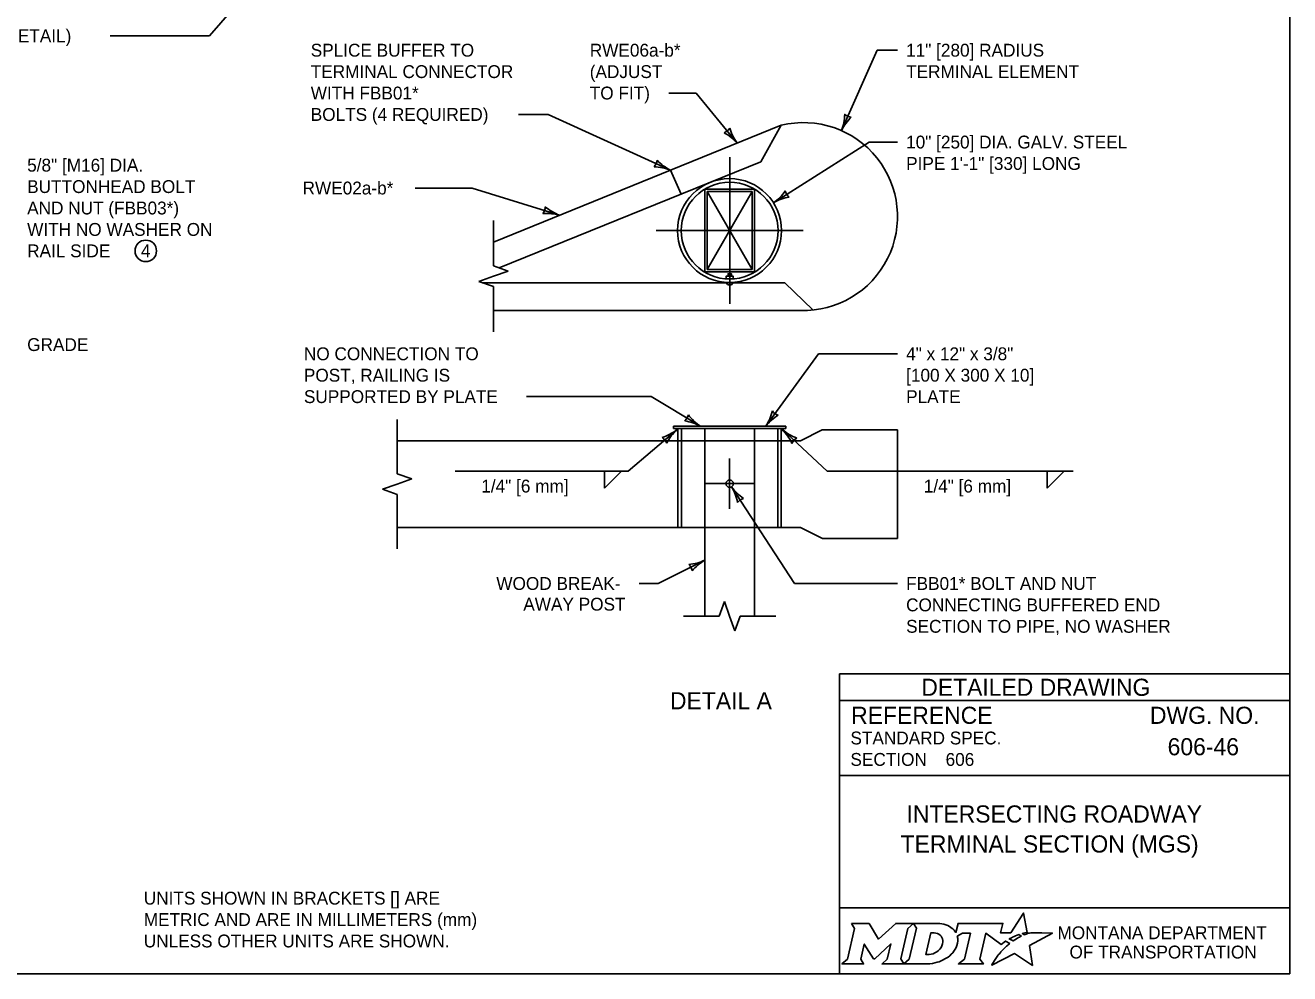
# Model space of a CAD drawing. Extents: x 49991.4 to 50021, y 49987.6 to 50011.4.
# Drawn here: x 50010.85 to 50016.75, y 49987.8 to 49992.23 of the extents above; entities that cross this region are included whole.
import ezdxf

# ---------------------------------------------------------------- set-up
doc = ezdxf.new("R2010")
doc.units = 0
for name, color, linetype in [('Default', 7, 'Continuous'), ('Level 1', 7, 'Continuous'), ('Level 2', 7, 'Continuous'), ('Level 3', 7, 'Continuous'), ('Level 4', 7, 'Continuous'), ('Level 5', 7, 'Continuous'), ('Level 6', 7, 'Continuous')]:
    doc.layers.add(name, color=color, linetype=linetype)

msp = doc.modelspace()

# ---------------------------------------------------------------- linework, layer by layer
at = {"layer": 'Default'}
for points in [[(50015.5126, 49987.9811), (50015.5023, 49987.9867), (50015.5139, 49987.9895), (50015.5255, 49987.9915), (50015.5081, 49988.0816), (50015.4486, 49987.9903), (50015.4013, 49987.9896), (50015.4116, 49988.0337), (50015.2024, 49988.0338), (50015.1923, 49987.9913), (50015.1865, 49987.9996)], [(50014.7056, 49988.0338), (50014.7197, 49988.0104), (50014.6862, 49987.8671), (50014.6605, 49987.8446), (50014.7621, 49987.8446), (50014.7486, 49987.8674), (50014.7648, 49987.9375), (50014.8085, 49987.8685), (50014.8138, 49987.8685), (50014.8889, 49987.938), (50014.8725, 49987.8669), (50014.8478, 49987.8449), (50014.9494, 49987.8449), (50014.9356, 49987.8682), (50014.9688, 49988.0106)], [(50014.9688, 49988.0106), (50014.9941, 49988.0338), (50014.9117, 49988.0338), (50014.8321, 49987.9608), (50014.7876, 49988.0335), (50014.7056, 49988.0338)], [(50015.1077, 49988.0338), (50014.9941, 49988.0338), (50015.0088, 49988.0109), (50014.9749, 49987.8671), (50014.9494, 49987.8449), (50015.06, 49987.8449)], [(50015.1317, 49987.9471), (50015.1305, 49987.939), (50015.1273, 49987.9297), (50015.1231, 49987.9215), (50015.1175, 49987.914), (50015.111, 49987.9071), (50015.1031, 49987.9008), (50015.0948, 49987.8961), (50015.0857, 49987.8922), (50015.0766, 49987.8899), (50015.0674, 49987.889), (50015.0515, 49987.889), (50015.0751, 49987.989), (50015.0911, 49987.989), (50015.0987, 49987.9884), (50015.1063, 49987.9865), (50015.1129, 49987.9835), (50015.119, 49987.9793), (50015.1238, 49987.9743), (50015.1275, 49987.9683), (50015.1302, 49987.9621), (50015.1318, 49987.9547), (50015.1318, 49987.9517), (50015.1317, 49987.9471)], [(50015.1991, 49987.9747), (50015.2237, 49987.9878), (50015.2606, 49987.9878), (50015.232, 49987.8673), (50015.2045, 49987.8446), (50015.3207, 49987.8446), (50015.3037, 49987.8675), (50015.3319, 49987.9877), (50015.4032, 49987.936), (50015.4243, 49987.9511), (50015.444, 49987.9402)], [(50015.3882, 49987.8843), (50015.3729, 49987.8599), (50015.3682, 49987.8524), (50015.3624, 49987.8438), (50015.3601, 49987.8395), (50015.4654, 49987.8926), (50015.5493, 49987.8375), (50015.5362, 49987.9302), (50015.6431, 49987.9886), (50015.5938, 49987.9894), (50015.5637, 49987.9898), (50015.5429, 49987.9901), (50015.5361, 49987.9886), (50015.5312, 49987.9874), (50015.5228, 49987.9851), (50015.5126, 49987.9811)], [(50015.4622, 49987.9535), (50015.4598, 49987.9518), (50015.4415, 49987.9614), (50015.4518, 49987.9671), (50015.4559, 49987.9693), (50015.4645, 49987.9733), (50015.4702, 49987.9759), (50015.4781, 49987.9789), (50015.4854, 49987.9816), (50015.4972, 49987.9742), (50015.4932, 49987.9721), (50015.4886, 49987.9696), (50015.4844, 49987.9674), (50015.4794, 49987.9645), (50015.4775, 49987.9634), (50015.4748, 49987.9618), (50015.4723, 49987.9604), (50015.47, 49987.9588), (50015.4674, 49987.957), (50015.4647, 49987.9552), (50015.4622, 49987.9535)], [(50015.1057, 49987.8522), (50015.1141, 49987.8548), (50015.1271, 49987.8602), (50015.1475, 49987.8712)], [(50015.4021, 49987.9004), (50015.4021, 49987.9004)]]:
    msp.add_lwpolyline(points, dxfattribs=at)
for centre, radius, start, end in [((50015.0868, 49987.9727), 0.1183, 300.91025, 339.13831), ((50015.1308, 49987.9554), 0.0709, 339.53292, 15.85821)]:
    msp.add_arc(centre, radius, start, end, dxfattribs=at)
for centre, major_axis, ratio, start_param, end_param in [((50015.1056, 49987.9864), (0.0834, -0.0037), 0.568097, 0.61298, 1.570796), ((50015.1612, 49987.9937), (0.0361, -0.0295), 0.469099, 1.225588, 1.570796), ((50015.4119, 49987.9106), (-0.0098, -0.0102), 0.016458, 3.141593, 6.279097), ((50015.4329, 49987.9305), (-0.0112, -0.0097), 0.021651, 3.157348, 6.283185), ((50015.3952, 49987.8923), (-0.00694, -0.00806), 0.008222, 0, 3.137361), ((50015.0603, 49987.9932), (0, 0.1484), 0.987302, 3.139398, 3.456847)]:
    msp.add_ellipse(centre, major_axis=major_axis, ratio=ratio, start_param=start_param, end_param=end_param, dxfattribs=at)
at = {"layer": 'Level 1'}
for p, q in [((50013.0344, 49991.2151), (50014.3767, 49991.76)), ((50014.2819, 49991.5899), (50014.3767, 49991.76)), ((50013.061, 49991.0947), (50014.2819, 49991.5899)), ((50013.8604, 49991.5504), (50013.9098, 49991.4389)), ((50014.0326, 49991.4504), (50014.2413, 49991.0872)), ((50014.0326, 49991.0872), (50014.2413, 49991.4504)), ((50014.0213, 49991.0757), (50014.2526, 49991.0757)), ((50012.9825, 49991.0253), (50014.3945, 49991.0253)), ((50014.5252, 49990.8978), (50014.3945, 49991.0253)), ((50013.0344, 49990.8959), (50014.4674, 49990.8959)), ((50013.8742, 49990.3549), (50014.3995, 49990.3549)), ((50013.8742, 49990.3549), (50013.8742, 49990.3451)), ((50013.8742, 49990.3451), (50014.3995, 49990.3451)), ((50013.8945, 49990.3451), (50013.8945, 49990.287)), ((50013.9115, 49990.3451), (50013.9115, 49990.287)), ((50014.0212, 49990.3451), (50014.0212, 49990.287)), ((50014.2525, 49990.3451), (50014.2525, 49990.287)), ((50014.3609, 49990.3451), (50014.3609, 49990.287)), ((50014.3779, 49990.3451), (50014.3779, 49990.287)), ((50014.3995, 49990.3549), (50014.3995, 49990.3451)), ((50014.5682, 49990.3383), (50014.4672, 49990.287)), ((50014.5682, 49990.3383), (50014.9202, 49990.3383)), ((50014.9202, 49990.3383), (50014.9202, 49989.8305)), ((50012.5854, 49990.287), (50014.4672, 49990.287)), ((50012.5854, 49989.8827), (50014.4672, 49989.8827)), ((50014.0212, 49989.8827), (50014.0212, 49989.4678)), ((50014.2525, 49989.8827), (50014.2525, 49989.4678)), ((50014.5697, 49989.8305), (50014.4672, 49989.8827)), ((50014.5697, 49989.8305), (50014.9202, 49989.8305))]:
    msp.add_line(p, q, dxfattribs=at)
for points in [[(49999.3835, 49998.9992), (50016.7501, 49998.9992), (50016.7501, 49987.7988), (49999.3835, 49987.7988)], [(50014.0326, 49991.4504), (50014.2413, 49991.4504), (50014.2413, 49991.0872), (50014.0326, 49991.0872)], [(50014.1211, 49991.043), (50014.1211, 49991.0559), (50014.1528, 49991.0559), (50014.1528, 49991.043)], [(50014.1291, 49991.0563), (50014.1291, 49991.0668), (50014.1447, 49991.0668), (50014.1447, 49991.0563)]]:
    msp.add_lwpolyline(points, close=True, dxfattribs=at)
msp.add_lwpolyline([(50014.0213, 49991.2468), (50014.0213, 49991.4619), (50014.2526, 49991.4619), (50014.2526, 49991.0757), (50014.0213, 49991.0757), (50014.0213, 49991.2468)], dxfattribs=at)
for centre, radius in [((50014.1364, 49991.2685), 0.2426), ((50014.1369, 49991.2682), 0.2257), ((50014.1369, 49990.0869), 0.017)]:
    msp.add_circle(centre, radius, dxfattribs=at)
for centre, radius, start, end in [((50014.4814, 49991.3341), 0.4385, 268.1763, 103.80595), ((50014.1369, 49991.0323), 0.018, 202.88216, 337.11784), ((50013.8758, 49990.3264), 0.0188, 0, 85.1307), ((50014.3967, 49990.3264), 0.0188, 94.48831, 180)]:
    msp.add_arc(centre, radius, start, end, dxfattribs=at)
at = {"layer": 'Level 2'}
msp.add_circle((50011.4126, 49991.1739), 0.05, dxfattribs=at)
at = {"layer": 'Level 3'}
for p, q in [((50011.7103, 49992.1778), (50012.0437, 49992.5637)), ((50011.2468, 49992.1778), (50011.7103, 49992.1778)), ((50014.6587, 49991.7352), (50014.8247, 49992.1107)), ((50014.8247, 49992.1107), (50014.9202, 49992.1107)), ((50013.9806, 49991.9107), (50013.8534, 49991.9107)), ((50014.1723, 49991.677), (50013.9806, 49991.9107)), ((50013.2899, 49991.8107), (50013.1509, 49991.8107)), ((50013.8604, 49991.5504), (50013.2899, 49991.8107)), ((50014.3412, 49991.3986), (50014.7882, 49991.6818)), ((50014.7882, 49991.6818), (50014.9202, 49991.6818)), ((50012.9361, 49991.4672), (50012.6691, 49991.4672)), ((50013.3433, 49991.3405), (50012.9361, 49991.4672)), ((50014.5511, 49990.6932), (50014.3052, 49990.3549)), ((50014.5511, 49990.6932), (50014.9202, 49990.6932)), ((50013.1888, 49990.4932), (50013.7711, 49990.4932)), ((50013.7711, 49990.4932), (50014.0007, 49990.3549)), ((50013.8901, 49990.3385), (50013.6634, 49990.1456)), ((50014.3829, 49990.3391), (50014.5922, 49990.1456)), ((50013.6634, 49990.1456), (50012.8554, 49990.1456)), ((50013.5529, 49990.0656), (50013.5529, 49990.1456)), ((50013.5529, 49990.0656), (50013.6329, 49990.1456)), ((50015.7393, 49990.1456), (50014.5922, 49990.1456)), ((50015.6177, 49990.0656), (50015.6177, 49990.1456)), ((50015.6177, 49990.0656), (50015.6977, 49990.1456)), ((50014.1461, 49990.0726), (50014.4392, 49989.6208)), ((50013.8025, 49989.6208), (50014.0212, 49989.73)), ((50013.7145, 49989.6208), (50013.8025, 49989.6208)), ((50014.4392, 49989.6208), (50014.9202, 49989.6208))]:
    msp.add_line(p, q, dxfattribs=at)
for centre, radius, start, end in [((50014.4406, 49991.817), 0.233, 339.43304, 358.68289), ((50014.859, 49991.6386), 0.2223, 134.06174, 154.24525), ((50014.7096, 49991.8528), 0.0548, 228.74455, 264.46691), ((50014.091, 49991.7761), 0.0548, 291.4961, 327.21846), ((50013.9997, 49991.5205), 0.233, 42.18459, 61.43444), ((50014.3499, 49991.8108), 0.2223, 196.81329, 216.9968), ((50013.7438, 49991.6036), 0.0548, 317.60842, 353.33078), ((50013.961, 49991.7487), 0.2223, 222.92561, 243.10912), ((50013.7742, 49991.3339), 0.233, 68.29691, 87.54676), ((50014.2072, 49991.5891), 0.233, 305.13102, 324.38087), ((50014.4522, 49991.2059), 0.2223, 99.75972, 119.94323), ((50014.4496, 49991.4671), 0.0548, 194.44253, 230.16489), ((50013.2214, 49991.3801), 0.0548, 324.10531, 359.82767), ((50013.2822, 49991.1156), 0.233, 74.7938, 94.04365), ((50013.4208, 49991.5488), 0.2223, 229.4225, 249.60601), ((50013.8908, 49990.4209), 0.0548, 311.12742, 346.84978), ((50014.123, 49990.5405), 0.2223, 216.44461, 236.62812), ((50014.1102, 49990.4824), 0.233, 326.81521, 346.06506), ((50014.4795, 49990.2169), 0.2223, 121.44391, 141.62742), ((50014.3806, 49990.4586), 0.0548, 216.12672, 251.84908), ((50013.753, 49990.5136), 0.2223, 287.86756, 308.05106), ((50014.0497, 49990.1688), 0.233, 133.23886, 152.48871), ((50013.8907, 49990.1495), 0.233, 61.81591, 81.06576), ((50014.2254, 49990.1822), 0.2223, 24.70017, 44.88367), ((50014.5325, 49990.5178), 0.233, 230.07147, 249.32132), ((50013.7924, 49990.2554), 0.0548, 22.55036, 58.27272), ((50014.4771, 49990.2521), 0.0548, 119.38297, 155.10534), ((50013.9547, 49989.9594), 0.2223, 10.42663, 30.61014), ((50014.3351, 49990.2089), 0.233, 215.79793, 235.04778), ((50014.2158, 49989.9651), 0.0548, 105.10944, 140.8318), ((50013.9255, 49989.9307), 0.2223, 275.3243, 295.50781), ((50013.9079, 49989.6701), 0.0548, 10.00711, 45.72947), ((50014.1402, 49989.5297), 0.233, 120.6956, 139.94545)]:
    msp.add_arc(centre, radius, start, end, dxfattribs=at)
at = {"layer": 'Level 4'}
for p, q in [((50013.8945, 49990.287), (50013.8945, 49989.8827)), ((50013.9115, 49990.287), (50013.9115, 49989.8827)), ((50014.0212, 49990.287), (50014.0212, 49989.8827)), ((50014.2525, 49990.287), (50014.2525, 49989.8827)), ((50014.3609, 49990.287), (50014.3609, 49989.8827)), ((50014.3779, 49990.287), (50014.3779, 49989.8827))]:
    msp.add_line(p, q, dxfattribs=at)
at = {"layer": 'Level 5'}
for p, q in [((50014.1369, 49991.6117), (50014.1369, 49990.9265)), ((50014.4791, 49991.2688), (50013.7938, 49991.2688)), ((50014.1368, 49989.9699), (50014.1368, 49990.2039)), ((50014.0199, 49990.0869), (50014.2538, 49990.0869)), ((50016.7501, 49989.1988), (50014.6501, 49989.1988)), ((50014.6501, 49989.1988), (50014.6501, 49987.7988)), ((50016.7501, 49989.0738), (50014.6501, 49989.0738)), ((50016.3862, 49988.8587), (50016.3862, 49988.8587)), ((50015.1444, 49988.7993), (50015.1444, 49988.7993)), ((50016.7501, 49988.7238), (50014.6501, 49988.7238)), ((50015.7001, 49988.4747), (50015.7001, 49988.4747)), ((50016.7501, 49988.1057), (50014.6501, 49988.1057))]:
    msp.add_line(p, q, dxfattribs=at)
at = {"layer": 'Level 6'}
for p, q in [((50013.0344, 49991.3151), (50013.0344, 49991.1041)), ((50013.0344, 49991.0555), (50012.9658, 49991.0312)), ((50013.103, 49991.0798), (50013.0344, 49991.1041)), ((50013.103, 49991.0798), (50013.0344, 49991.0555)), ((50013.0344, 49991.0069), (50012.9658, 49991.0312)), ((50013.0344, 49991.0069), (50013.0344, 49990.7959)), ((50012.5854, 49990.387), (50012.5854, 49990.1335)), ((50012.654, 49990.1092), (50012.5854, 49990.1335)), ((50012.654, 49990.1092), (50012.5854, 49990.0849)), ((50012.5854, 49990.0849), (50012.5168, 49990.0606)), ((50012.5854, 49990.0363), (50012.5168, 49990.0606)), ((50012.5854, 49990.0363), (50012.5854, 49989.7827)), ((50014.1125, 49989.5363), (50014.0882, 49989.4678)), ((50014.1125, 49989.5363), (50014.1368, 49989.4678)), ((50013.9212, 49989.4678), (50014.0882, 49989.4678)), ((50014.1368, 49989.4678), (50014.1611, 49989.3993)), ((50014.1854, 49989.4678), (50014.1611, 49989.3993)), ((50014.1854, 49989.4678), (50014.3525, 49989.4678))]:
    msp.add_line(p, q, dxfattribs=at)

# ---------------------------------------------------------------- texts
at = {"layer": 'Default'}
for s, p in [('MONTANA DEPARTMENT', (50015.6663, 49987.96)), ('OF TRANSPORTATION', (50015.7225, 49987.87))]:
    msp.add_text(s, height=0.06, dxfattribs=at).set_placement(p)
at = {"layer": 'Level 2'}
for s, height, p in [('(SEE DETAIL)', 0.06, (50010.5479, 49992.1478)), ('SPLICE BUFFER TO', 0.06, (50012.1821, 49992.0807)), ('RWE06a-b*', 0.06, (50013.4841, 49992.0807)), ('11" [280] RADIUS', 0.06, (50014.9602, 49992.0807)), ('TERMINAL CONNECTOR', 0.06, (50012.1821, 49991.9807)), ('(ADJUST', 0.06, (50013.4841, 49991.9807)), ('TERMINAL ELEMENT', 0.06, (50014.9602, 49991.9807)), ('WITH FBB01*', 0.06, (50012.1821, 49991.8807)), ('TO FIT)', 0.06, (50013.4841, 49991.8807)), ('BOLTS (4 REQUIRED)', 0.06, (50012.1821, 49991.7807)), ('10" [250] DIA. GALV. STEEL', 0.06, (50014.9602, 49991.6518)), ('5/8" [M16] DIA. ', 0.06, (50010.8589, 49991.5439)), ('PIPE 1\'-1" [330] LONG', 0.06, (50014.9602, 49991.5518)), ('BUTTONHEAD BOLT ', 0.06, (50010.8589, 49991.4439)), ('RWE02a-b*', 0.06, (50012.144, 49991.4372)), ('AND NUT (FBB03*)', 0.06, (50010.8589, 49991.3439)), ('WITH NO WASHER ON', 0.06, (50010.8589, 49991.2439)), ('RAIL SIDE', 0.06, (50010.8589, 49991.1439)), ('4', 0.06, (50011.3898, 49991.1439)), ('GRADE', 0.06, (50010.8589, 49990.7062)), ('NO CONNECTION TO', 0.06, (50012.1502, 49990.6632)), ('4" x 12" x 3/8" ', 0.06, (50014.9602, 49990.6632)), ('POST, RAILING IS ', 0.06, (50012.1502, 49990.5632)), ('[100 X 300 X 10]', 0.06, (50014.9602, 49990.5632)), ('SUPPORTED BY PLATE', 0.06, (50012.1502, 49990.4632)), ('PLATE', 0.06, (50014.9602, 49990.4632)), ('1/4" [6 mm]', 0.06, (50012.9779, 49990.0456)), ('1/4" [6 mm]', 0.06, (50015.0427, 49990.0456)), ('WOOD BREAK-', 0.06, (50013.048, 49989.5908)), ('FBB01* BOLT AND NUT', 0.06, (50014.9602, 49989.5908)), ('AWAY POST', 0.06, (50013.1739, 49989.4942)), ('CONNECTING BUFFERED END', 0.06, (50014.9602, 49989.4908)), ('SECTION TO PIPE, NO WASHER', 0.06, (50014.9602, 49989.3908)), ('DETAIL A', 0.08, (50013.8583, 49989.0333)), ('606-46', 0.08, (50016.1804, 49988.8187)), ('606', 0.06, (50015.1444, 49988.7693)), ('INTERSECTING ROADWAY', 0.08, (50014.9619, 49988.5047)), ('TERMINAL SECTION (MGS)', 0.08, (50014.9344, 49988.3647)), ('UNITS SHOWN IN BRACKETS [] ARE ', 0.06, (50011.403, 49988.1216)), ('METRIC AND ARE IN MILLIMETERS (mm) ', 0.06, (50011.403, 49988.0216)), ('UNLESS OTHER UNITS ARE SHOWN.', 0.06, (50011.403, 49987.9216))]:
    msp.add_text(s, height=height, dxfattribs=at).set_placement(p)
at = {"layer": 'Level 5'}
for s, height, p in [('DETAILED DRAWING', 0.0799, (50015.0311, 49989.0963)), ('REFERENCE', 0.08, (50014.7037, 49988.9654)), ('DWG. NO.', 0.08, (50016.0979, 49988.9654)), ('STANDARD SPEC.', 0.06, (50014.7004, 49988.8694)), ('SECTION', 0.06, (50014.7004, 49988.7694))]:
    msp.add_text(s, height=height, dxfattribs=at).set_placement(p)

doc.saveas('drawing.dxf')
